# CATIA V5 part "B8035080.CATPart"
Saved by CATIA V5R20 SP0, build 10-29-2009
Part number: B8035080
Revision: 4
Definition: design
Nomenclature: B8035080
Source: made
Description: NOT SPECIFIED
Bounding box of the stored display mesh (mm): x -35 to 35, y -35 to 35, z 0 to 80
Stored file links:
  C:\Users\Utente\Desktop\3D files B803\B8035080.CATPart
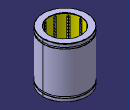
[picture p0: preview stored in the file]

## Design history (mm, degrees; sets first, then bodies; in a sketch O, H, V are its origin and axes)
Body1 "MANIFOLD_SOLID_BREP #38" (main body)
  Solid1: solid without history
Body2 "MANIFOLD_SOLID_BREP #76"
  Solid2: solid without history
Body3 "MANIFOLD_SOLID_BREP #114"
  Solid3: solid without history
Body4 "MANIFOLD_SOLID_BREP #152"
  Solid4: solid without history
Body5 "MANIFOLD_SOLID_BREP #190"
  Solid5: solid without history
Body6 "MANIFOLD_SOLID_BREP #228"
  Solid6: solid without history
Body7 "MANIFOLD_SOLID_BREP #266"
  Solid7: solid without history
Body8 "MANIFOLD_SOLID_BREP #304"
  Solid8: solid without history
Body9 "MANIFOLD_SOLID_BREP #2814"
  Solid9: solid without history
Body10 "MANIFOLD_SOLID_BREP #2852"
  Solid10: solid without history
Body11 "MANIFOLD_SOLID_BREP #2890"
  Solid11: solid without history
Body12 "MANIFOLD_SOLID_BREP #2928"
  Solid12: solid without history
Body13 "MANIFOLD_SOLID_BREP #2966"
  Solid13: solid without history
Body14 "MANIFOLD_SOLID_BREP #3004"
  Solid14: solid without history
Body15 "MANIFOLD_SOLID_BREP #3042"
  Solid15: solid without history
Body16 "MANIFOLD_SOLID_BREP #3080"
  Solid16: solid without history
Body17 "MANIFOLD_SOLID_BREP #3118"
  Solid17: solid without history
Body18 "MANIFOLD_SOLID_BREP #3156"
  Solid18: solid without history
Body19 "MANIFOLD_SOLID_BREP #3194"
  Solid19: solid without history
Body20 "MANIFOLD_SOLID_BREP #3232"
  Solid20: solid without history
Body21 "MANIFOLD_SOLID_BREP #3270"
  Solid21: solid without history
Body22 "MANIFOLD_SOLID_BREP #3308"
  Solid22: solid without history
Body23 "MANIFOLD_SOLID_BREP #3346"
  Solid23: solid without history
Body24 "MANIFOLD_SOLID_BREP #3384"
  Solid24: solid without history
Body25 "MANIFOLD_SOLID_BREP #3422"
  Solid25: solid without history
Body26 "MANIFOLD_SOLID_BREP #3460"
  Solid26: solid without history
Body27 "MANIFOLD_SOLID_BREP #3498"
  Solid27: solid without history
Body28 "MANIFOLD_SOLID_BREP #3536"
  Solid28: solid without history
Body29 "MANIFOLD_SOLID_BREP #3574"
  Solid29: solid without history
Body30 "MANIFOLD_SOLID_BREP #3612"
  Solid30: solid without history
Body31 "MANIFOLD_SOLID_BREP #3650"
  Solid31: solid without history
Body32 "MANIFOLD_SOLID_BREP #3688"
  Solid32: solid without history
Body33 "MANIFOLD_SOLID_BREP #3726"
  Solid33: solid without history
Body34 "MANIFOLD_SOLID_BREP #3764"
  Solid34: solid without history
Body35 "MANIFOLD_SOLID_BREP #3802"
  Solid35: solid without history
Body36 "MANIFOLD_SOLID_BREP #3840"
  Solid36: solid without history
Body37 "MANIFOLD_SOLID_BREP #3878"
  Solid37: solid without history
Body38 "MANIFOLD_SOLID_BREP #3916"
  Solid38: solid without history
Body39 "MANIFOLD_SOLID_BREP #3954"
  Solid39: solid without history
Body40 "MANIFOLD_SOLID_BREP #3992"
  Solid40: solid without history
Body41 "MANIFOLD_SOLID_BREP #4030"
  Solid41: solid without history
Body42 "MANIFOLD_SOLID_BREP #4068"
  Solid42: solid without history
Body43 "MANIFOLD_SOLID_BREP #4106"
  Solid43: solid without history
Body44 "MANIFOLD_SOLID_BREP #4144"
  Solid44: solid without history
Body45 "MANIFOLD_SOLID_BREP #4182"
  Solid45: solid without history
Body46 "MANIFOLD_SOLID_BREP #4220"
  Solid46: solid without history
Body47 "MANIFOLD_SOLID_BREP #4258"
  Solid47: solid without history
Body48 "MANIFOLD_SOLID_BREP #4296"
  Solid48: solid without history
Body49 "MANIFOLD_SOLID_BREP #4334"
  Solid49: solid without history
Body50 "MANIFOLD_SOLID_BREP #4372"
  Solid50: solid without history
Body51 "MANIFOLD_SOLID_BREP #4410"
  Solid51: solid without history
Body52 "MANIFOLD_SOLID_BREP #4448"
  Solid52: solid without history
Body53 "MANIFOLD_SOLID_BREP #4486"
  Solid53: solid without history
Body54 "MANIFOLD_SOLID_BREP #4524"
  Solid54: solid without history
Body55 "MANIFOLD_SOLID_BREP #4562"
  Solid55: solid without history
Body56 "MANIFOLD_SOLID_BREP #4600"
  Solid56: solid without history
Body57 "MANIFOLD_SOLID_BREP #4638"
  Solid57: solid without history
Body58 "MANIFOLD_SOLID_BREP #4676"
  Solid58: solid without history
Body59 "MANIFOLD_SOLID_BREP #4714"
  Solid59: solid without history
Body60 "MANIFOLD_SOLID_BREP #4752"
  Solid60: solid without history
Body61 "MANIFOLD_SOLID_BREP #4790"
  Solid61: solid without history
Body62 "MANIFOLD_SOLID_BREP #4828"
  Solid62: solid without history
Body63 "MANIFOLD_SOLID_BREP #4866"
  Solid63: solid without history
Body64 "MANIFOLD_SOLID_BREP #4904"
  Solid64: solid without history
Body65 "MANIFOLD_SOLID_BREP #4942"
  Solid65: solid without history
Body66 "MANIFOLD_SOLID_BREP #4980"
  Solid66: solid without history
Body67 "MANIFOLD_SOLID_BREP #5018"
  Solid67: solid without history
Body68 "MANIFOLD_SOLID_BREP #5056"
  Solid68: solid without history
Body69 "MANIFOLD_SOLID_BREP #5094"
  Solid69: solid without history
Body70 "MANIFOLD_SOLID_BREP #5132"
  Solid70: solid without history
Body71 "MANIFOLD_SOLID_BREP #5170"
  Solid71: solid without history
Body72 "MANIFOLD_SOLID_BREP #5208"
  Solid72: solid without history
Body73 "MANIFOLD_SOLID_BREP #5246"
  Solid73: solid without history
Body74 "MANIFOLD_SOLID_BREP #5284"
  Solid74: solid without history
Body75 "MANIFOLD_SOLID_BREP #5322"
  Solid75: solid without history
Body76 "MANIFOLD_SOLID_BREP #5360"
  Solid76: solid without history
Body77 "MANIFOLD_SOLID_BREP #5398"
  Solid77: solid without history
Body78 "MANIFOLD_SOLID_BREP #5436"
  Solid78: solid without history
Body79 "MANIFOLD_SOLID_BREP #5474"
  Solid79: solid without history
Body80 "MANIFOLD_SOLID_BREP #5512"
  Solid80: solid without history
Body81 "MANIFOLD_SOLID_BREP #5550"
  Solid81: solid without history
Body82 "MANIFOLD_SOLID_BREP #5588"
  Solid82: solid without history
Body83 "MANIFOLD_SOLID_BREP #5626"
  Solid83: solid without history
Body84 "MANIFOLD_SOLID_BREP #5664"
  Solid84: solid without history
Body85 "MANIFOLD_SOLID_BREP #5702"
  Solid85: solid without history
Body86 "MANIFOLD_SOLID_BREP #5740"
  Solid86: solid without history
Body87 "MANIFOLD_SOLID_BREP #5778"
  Solid87: solid without history
Body88 "MANIFOLD_SOLID_BREP #5816"
  Solid88: solid without history
Body89 "MANIFOLD_SOLID_BREP #5854"
  Solid89: solid without history
Body90 "MANIFOLD_SOLID_BREP #5892"
  Solid90: solid without history
Body91 "MANIFOLD_SOLID_BREP #5930"
  Solid91: solid without history
Body92 "MANIFOLD_SOLID_BREP #5968"
  Solid92: solid without history
Body93 "MANIFOLD_SOLID_BREP #6006"
  Solid93: solid without history
Body94 "MANIFOLD_SOLID_BREP #6044"
  Solid94: solid without history
Body95 "MANIFOLD_SOLID_BREP #6082"
  Solid95: solid without history
Body96 "MANIFOLD_SOLID_BREP #6120"
  Solid96: solid without history
Body97 "MANIFOLD_SOLID_BREP #6158"
  Solid97: solid without history
Body98 "MANIFOLD_SOLID_BREP #6196"
  Solid98: solid without history
Body99 "MANIFOLD_SOLID_BREP #6234"
  Solid99: solid without history
Body100 "MANIFOLD_SOLID_BREP #6272"
  Solid100: solid without history
Body101 "MANIFOLD_SOLID_BREP #6310"
  Solid101: solid without history
Body102 "MANIFOLD_SOLID_BREP #6348"
  Solid102: solid without history
Body103 "MANIFOLD_SOLID_BREP #6386"
  Solid103: solid without history
Body104 "MANIFOLD_SOLID_BREP #6424"
  Solid104: solid without history
Body105 "MANIFOLD_SOLID_BREP #6462"
  Solid105: solid without history
Body106 "MANIFOLD_SOLID_BREP #6500"
  Solid106: solid without history
Body107 "MANIFOLD_SOLID_BREP #6538"
  Solid107: solid without history
Body108 "MANIFOLD_SOLID_BREP #6576"
  Solid108: solid without history
Body109 "MANIFOLD_SOLID_BREP #6614"
  Solid109: solid without history
Body110 "MANIFOLD_SOLID_BREP #6652"
  Solid110: solid without history
Body111 "MANIFOLD_SOLID_BREP #6690"
  Solid111: solid without history
Body112 "MANIFOLD_SOLID_BREP #6728"
  Solid112: solid without history
Body113 "MANIFOLD_SOLID_BREP #6766"
  Solid113: solid without history
Body114 "MANIFOLD_SOLID_BREP #6804"
  Solid114: solid without history
Body115 "MANIFOLD_SOLID_BREP #6842"
  Solid115: solid without history
Body116 "MANIFOLD_SOLID_BREP #6880"
  Solid116: solid without history
Body117 "MANIFOLD_SOLID_BREP #6918"
  Solid117: solid without history
Body118 "MANIFOLD_SOLID_BREP #6956"
  Solid118: solid without history
Body119 "MANIFOLD_SOLID_BREP #6994"
  Solid119: solid without history
Body120 "MANIFOLD_SOLID_BREP #7032"
  Solid120: solid without history
Body121 "MANIFOLD_SOLID_BREP #7070"
  Solid121: solid without history
Body122 "MANIFOLD_SOLID_BREP #7108"
  Solid122: solid without history
Body123 "MANIFOLD_SOLID_BREP #7146"
  Solid123: solid without history
Body124 "MANIFOLD_SOLID_BREP #7184"
  Solid124: solid without history
Body125 "MANIFOLD_SOLID_BREP #7222"
  Solid125: solid without history
Body126 "MANIFOLD_SOLID_BREP #7260"
  Solid126: solid without history
Body127 "MANIFOLD_SOLID_BREP #7298"
  Solid127: solid without history
Body128 "MANIFOLD_SOLID_BREP #7336"
  Solid128: solid without history
Body129 "MANIFOLD_SOLID_BREP #7374"
  Solid129: solid without history
Body130 "MANIFOLD_SOLID_BREP #7412"
  Solid130: solid without history
Body131 "MANIFOLD_SOLID_BREP #7450"
  Solid131: solid without history
Body132 "MANIFOLD_SOLID_BREP #7488"
  Solid132: solid without history
Body133 "MANIFOLD_SOLID_BREP #7526"
  Solid133: solid without history
Body134 "MANIFOLD_SOLID_BREP #7564"
  Solid134: solid without history
Body135 "MANIFOLD_SOLID_BREP #7602"
  Solid135: solid without history
Body136 "MANIFOLD_SOLID_BREP #7640"
  Solid136: solid without history
Body137 "MANIFOLD_SOLID_BREP #7678"
  Solid137: solid without history
Body138 "MANIFOLD_SOLID_BREP #7716"
  Solid138: solid without history
Body139 "MANIFOLD_SOLID_BREP #7754"
  Solid139: solid without history
Body140 "MANIFOLD_SOLID_BREP #7792"
  Solid140: solid without history
Body141 "MANIFOLD_SOLID_BREP #7830"
  Solid141: solid without history
Body142 "MANIFOLD_SOLID_BREP #7868"
  Solid142: solid without history
Body143 "MANIFOLD_SOLID_BREP #7906"
  Solid143: solid without history
Body144 "MANIFOLD_SOLID_BREP #7944"
  Solid144: solid without history
Body145 "MANIFOLD_SOLID_BREP #7982"
  Solid145: solid without history
Body146 "MANIFOLD_SOLID_BREP #8020"
  Solid146: solid without history
Body147 "MANIFOLD_SOLID_BREP #8058"
  Solid147: solid without history
Body148 "MANIFOLD_SOLID_BREP #8096"
  Solid148: solid without history
Body149 "MANIFOLD_SOLID_BREP #8134"
  Solid149: solid without history
Body150 "MANIFOLD_SOLID_BREP #8172"
  Solid150: solid without history
Body151 "MANIFOLD_SOLID_BREP #8210"
  Solid151: solid without history
Body152 "MANIFOLD_SOLID_BREP #8248"
  Solid152: solid without history
Body153 "MANIFOLD_SOLID_BREP #8286"
  Solid153: solid without history
Body154 "MANIFOLD_SOLID_BREP #8324"
  Solid154: solid without history
Body155 "MANIFOLD_SOLID_BREP #8362"
  Solid155: solid without history
Body156 "MANIFOLD_SOLID_BREP #8400"
  Solid156: solid without history
Body157 "MANIFOLD_SOLID_BREP #8438"
  Solid157: solid without history
Body158 "MANIFOLD_SOLID_BREP #8476"
  Solid158: solid without history
Body159 "MANIFOLD_SOLID_BREP #8514"
  Solid159: solid without history
Body160 "MANIFOLD_SOLID_BREP #8552"
  Solid160: solid without history
Body161 "MANIFOLD_SOLID_BREP #8590"
  Solid161: solid without history
Body162 "MANIFOLD_SOLID_BREP #8628"
  Solid162: solid without history
Body163 "MANIFOLD_SOLID_BREP #8666"
  Solid163: solid without history
Body164 "MANIFOLD_SOLID_BREP #8704"
  Solid164: solid without history
Body165 "MANIFOLD_SOLID_BREP #8742"
  Solid165: solid without history
Body166 "MANIFOLD_SOLID_BREP #8780"
  Solid166: solid without history
Body167 "MANIFOLD_SOLID_BREP #8818"
  Solid167: solid without history
Body168 "MANIFOLD_SOLID_BREP #8856"
  Solid168: solid without history
Body169 "MANIFOLD_SOLID_BREP #8894"
  Solid169: solid without history
Body170 "MANIFOLD_SOLID_BREP #8932"
  Solid170: solid without history
Body171 "MANIFOLD_SOLID_BREP #8970"
  Solid171: solid without history
Body172 "MANIFOLD_SOLID_BREP #9008"
  Solid172: solid without history
Body173 "MANIFOLD_SOLID_BREP #9046"
  Solid173: solid without history
Body174 "MANIFOLD_SOLID_BREP #9084"
  Solid174: solid without history
Body175 "MANIFOLD_SOLID_BREP #9122"
  Solid175: solid without history
Body176 "MANIFOLD_SOLID_BREP #9160"
  Solid176: solid without history
Body177 "MANIFOLD_SOLID_BREP #9198"
  Solid177: solid without history
Body178 "MANIFOLD_SOLID_BREP #9236"
  Solid178: solid without history
Body179 "MANIFOLD_SOLID_BREP #9274"
  Solid179: solid without history
Body180 "MANIFOLD_SOLID_BREP #9312"
  Solid180: solid without history
Body181 "MANIFOLD_SOLID_BREP #9350"
  Solid181: solid without history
